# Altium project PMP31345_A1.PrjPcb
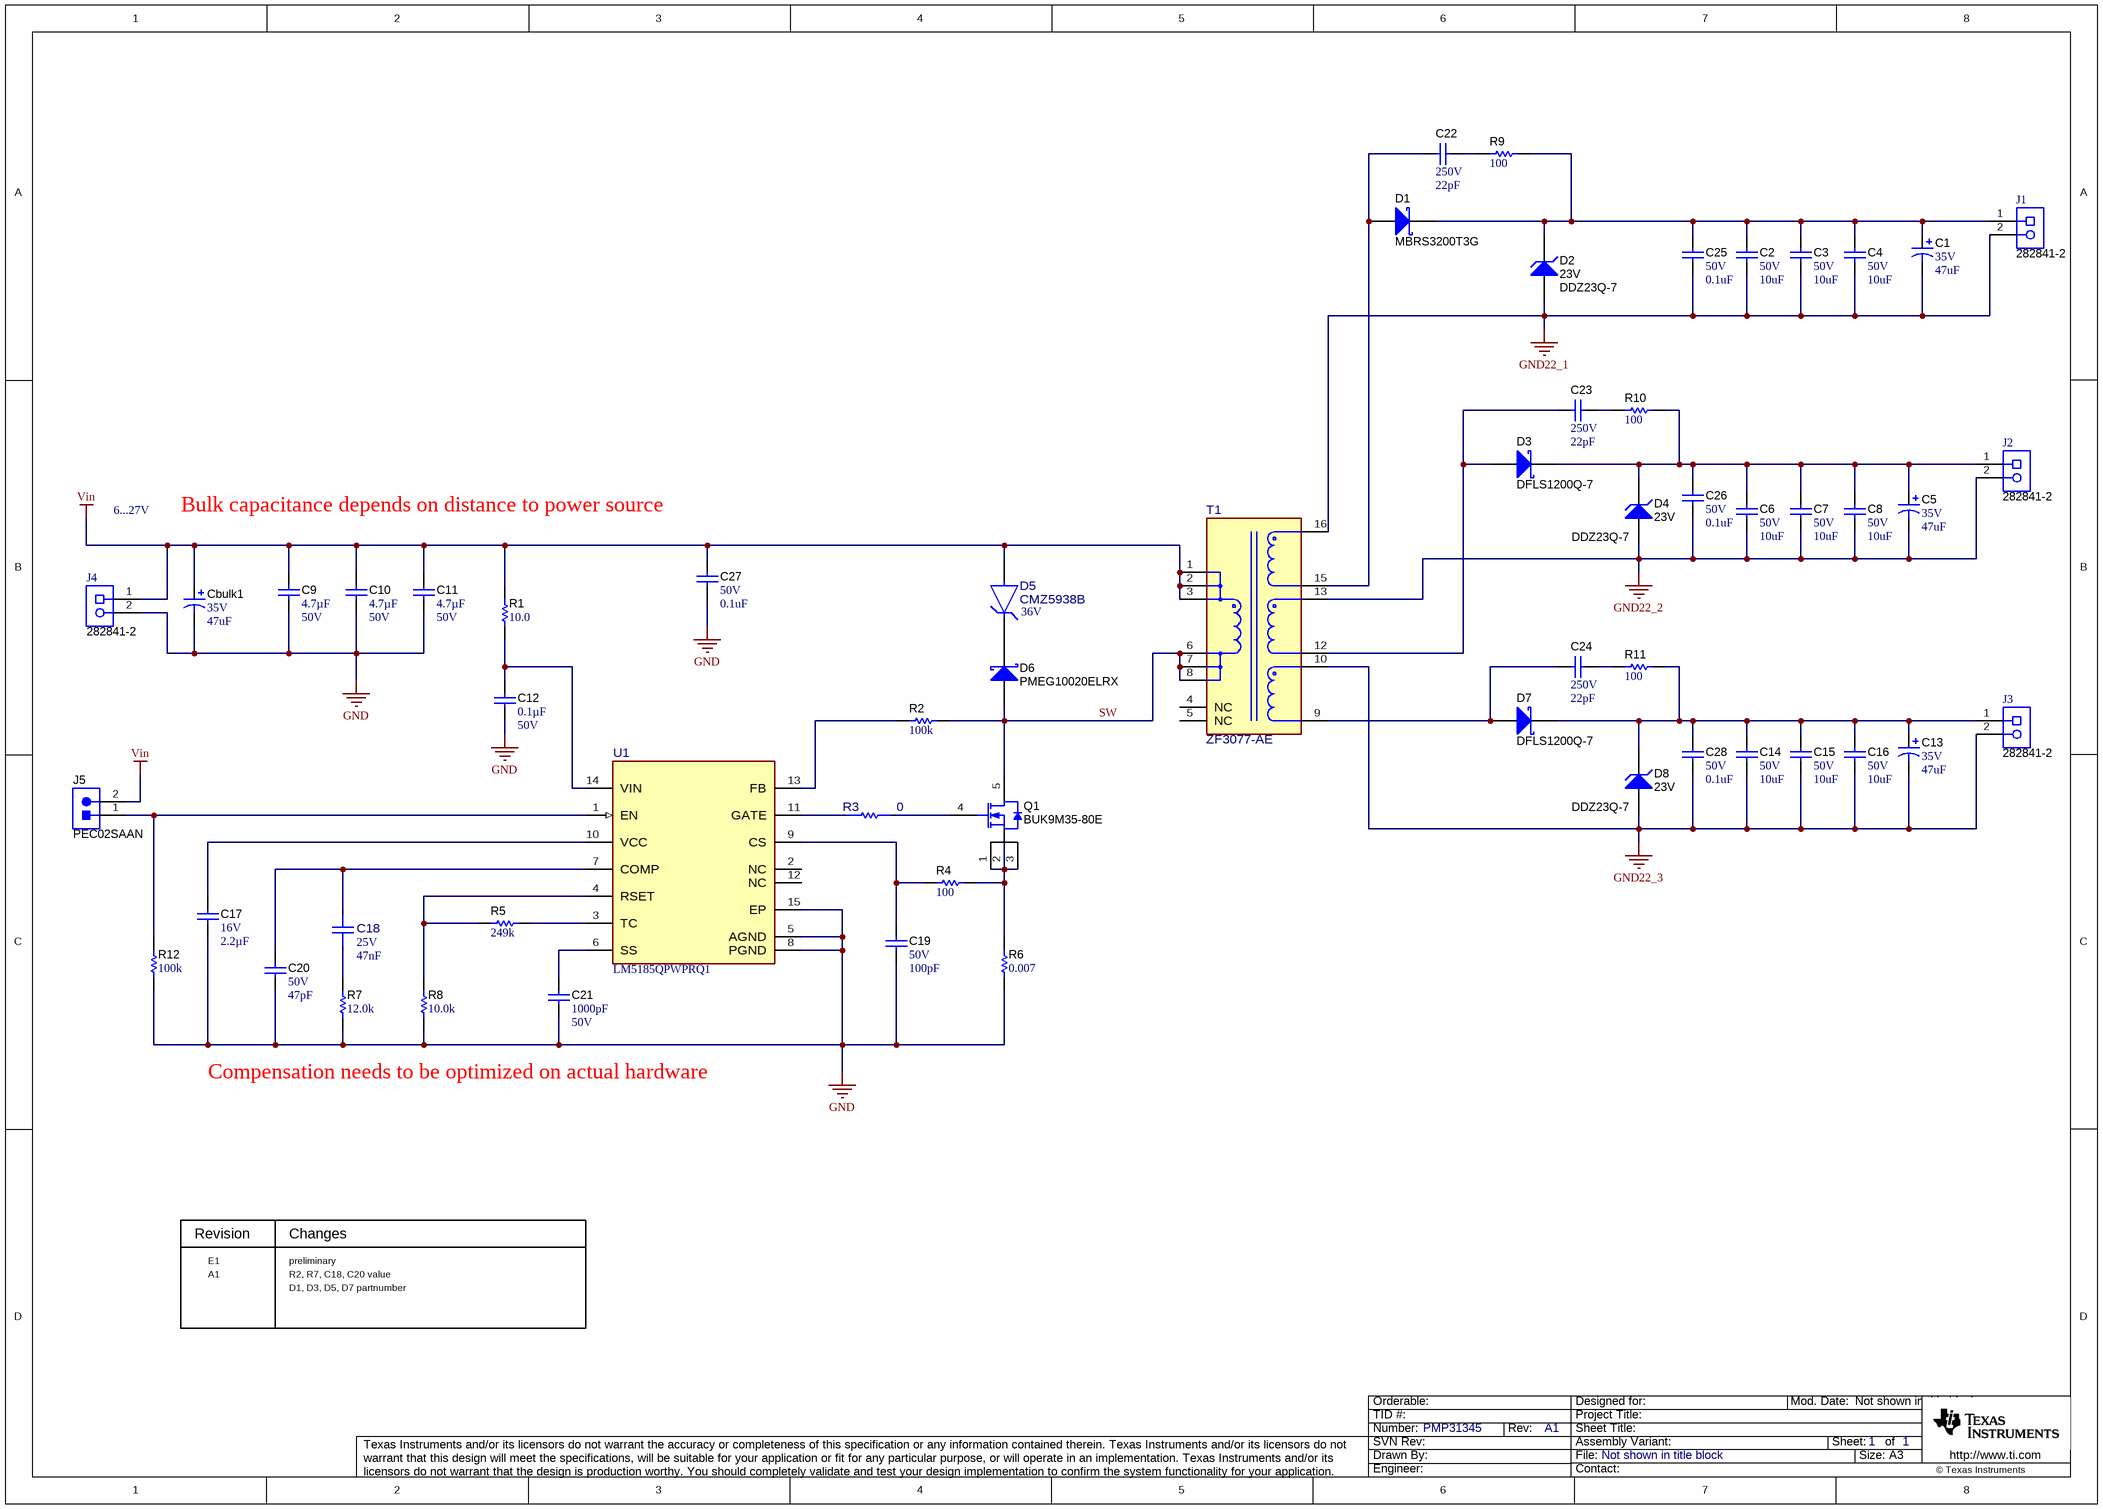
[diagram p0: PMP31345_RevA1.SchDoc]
PRJ_Number: PMP31345; SCH_Rev: A1
1 sheet, 57 parts. Net scope: global (net labels, ports and power ports of the same name join across sheets).
Board file: PMP31345_E1.PcbDoc

## Sheet PMP31345_RevA1.SchDoc
size A3; Date: Not shown in title block; ApprovedBy: Not shown in title block; CheckedBy: Not shown in title block; Author: Not shown in title block; CompanyName: Not shown in title block; Engineer: Not shown in title block; Organization: Not shown in title block; Address1: Not shown in title block; Address2: Not shown in title block; Address3: Not shown in title block; Address4: Not shown in title block; DocumentNumber: 1; Revision: Use project parameter SCH_Rev; SheetNumber: 1; SheetTotal: 1; PageSetup: Record=PageOptions¦CenterHorizontal=True¦CenterVertical=True¦PrintScale=0.69¦XCorrection=1.00¦YCorrection=1.00¦PrintKind=0¦BorderSize=5000000¦LeftOffset=0¦BottomOffset=0¦Orientation=2¦PaperLength=1000¦PaperWidth=1000¦Scale=100¦PaperSource=15¦PrintQuality=600¦MediaType=1¦DitherType=10¦PaperKind=Letter¦PrintScaleMode=1

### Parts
C1  VDC_V: 35V  ValueDisplayed: 47uF  [SM_RADIAL_D]  (hidden comment: EEE-FK1V470P)
C2  VDC_V: 50V  ValueDisplayed: 10uF  [1210_270]  (hidden comment: UMJ325KB7106KMHT)
C3  VDC_V: 50V  ValueDisplayed: 10uF  [1210_270]  (hidden comment: UMJ325KB7106KMHT)
C4  VDC_V: 50V  ValueDisplayed: 10uF  [1210_270]  (hidden comment: UMJ325KB7106KMHT)
C5  VDC_V: 35V  ValueDisplayed: 47uF  [SM_RADIAL_D]  (hidden comment: EEE-FK1V470P)
C6  VDC_V: 50V  ValueDisplayed: 10uF  [1210_270]  (hidden comment: UMJ325KB7106KMHT)
C7  VDC_V: 50V  ValueDisplayed: 10uF  [1210_270]  (hidden comment: UMJ325KB7106KMHT)
C8  VDC_V: 50V  ValueDisplayed: 10uF  [1210_270]  (hidden comment: UMJ325KB7106KMHT)
C9  ValueDisplayed: 4.7µF  VDC_V: 50V  [1210_270]  (hidden comment: GCM32ER71H475KA55L)
C10  ValueDisplayed: 4.7µF  VDC_V: 50V  [1210_270]  (hidden comment: GCM32ER71H475KA55L)
C11  ValueDisplayed: 4.7µF  VDC_V: 50V  [1210_270]  (hidden comment: GCM32ER71H475KA55L)
C12  ValueDisplayed: 0.1µF  VDC_V: 50V  [0402]  (hidden comment: CGA2B3X7R1H104K050BD)
C13  VDC_V: 35V  ValueDisplayed: 47uF  [SM_RADIAL_D]  (hidden comment: EEE-FK1V470P)
C14  VDC_V: 50V  ValueDisplayed: 10uF  [1210_270]  (hidden comment: UMJ325KB7106KMHT)
C15  VDC_V: 50V  ValueDisplayed: 10uF  [1210_270]  (hidden comment: UMJ325KB7106KMHT)
C16  VDC_V: 50V  ValueDisplayed: 10uF  [1210_270]  (hidden comment: UMJ325KB7106KMHT)
C17  VDC_V: 16V  ValueDisplayed: 2.2µF  [0402]  (hidden comment: GRT155C81C225ME13D)
C18  VDC_V: 25V  ValueDisplayed: 47nF  [FP-GCM155R71E473KA55D_0402-MFG]  (hidden comment: GCM155R71E473KA55D)
C19  VDC_V: 50V  ValueDisplayed: 100pF  [0402]  (hidden comment: CGA2B2C0G1H101J050BA)
C20  VDC_V: 50V  ValueDisplayed: 47pF  [0402]  (hidden comment: CGA2B2NP01H470J050BA)
C21  ValueDisplayed: 1000pF  VDC_V: 50V  [0402]  (hidden comment: CGA2B2X8R1H102K050BA)
C22  VDC_V: 250V  ValueDisplayed: 22pF  [0603]  (hidden comment: 251R14S220JV4T)
C23  VDC_V: 250V  ValueDisplayed: 22pF  [0603]  (hidden comment: 251R14S220JV4T)
C24  VDC_V: 250V  ValueDisplayed: 22pF  [0603]  (hidden comment: 251R14S220JV4T)
C25  VDC_V: 50V  ValueDisplayed: 0.1uF  [0402]  (hidden comment: GCM155R71H104KE02D)
C26  VDC_V: 50V  ValueDisplayed: 0.1uF  [0402]  (hidden comment: GCM155R71H104KE02D)
C27  VDC_V: 50V  ValueDisplayed: 0.1uF  [0402]  (hidden comment: GCM155R71H104KE02D)
C28  VDC_V: 50V  ValueDisplayed: 0.1uF  [0402]  (hidden comment: GCM155R71H104KE02D)
Cbulk1  VDC_V: 35V  ValueDisplayed: 47uF  [SM_RADIAL_D]  (hidden comment: EEE-FK1V470P)
D1  MBRS3200T3G  [SMB]
D2  DDZ23Q-7  value 23V  [SOD-123]
D3  DFLS1200Q-7  [FP-DFLS1200Q-7_PowerDI123-MFG]
D4  DDZ23Q-7  value 23V  [SOD-123]
D5  CMZ5938B  Vz_V: 36V  [FP-SMAJ5926B-TP_SMA-MFG]
D6  PMEG10020ELRX  [SOD-123W]
D7  DFLS1200Q-7  [FP-DFLS1200Q-7_PowerDI123-MFG]
D8  DDZ23Q-7  value 23V  [SOD-123]
J1  282841-2  [TEC_282841-2]
J2  282841-2  [TEC_282841-2]
J3  282841-2  [TEC_282841-2]
J4  282841-2  [TEC_282841-2]
J5  PEC02SAAN  [CONN_PEC02SAAN]
Q1  BUK9M35-80E  [LFPAK33]
R1  ValueDisplayed: 10.0  [0603]  (hidden comment: CRCW060310R0FKEA)
R2  ValueDisplayed: 100k  [0603]  (hidden comment: CRCW0603100KFKEA)
R3  0  [FP-ERJ-H3G0R00V_0603-MFG]
R4  ValueDisplayed: 100  [0402]  (hidden comment: RMCF0402JT100R)
R5  ValueDisplayed: 249k  [0402]  (hidden comment: CRCW0402249KFKED)
R6  ValueDisplayed: 0.007  [PE1206]  (hidden comment: PE1206FRF470R007L)
R7  ValueDisplayed: 12.0k  [0402]  (hidden comment: CRCW040212K0FKED)
R8  ValueDisplayed: 10.0k  [0402]  (hidden comment: ERJPA2F1002X)
R9  ValueDisplayed: 100  [1206]  (hidden comment: RC1206FR-07100RL)
R10  ValueDisplayed: 100  [1206]  (hidden comment: RC1206FR-07100RL)
R11  ValueDisplayed: 100  [1206]  (hidden comment: RC1206FR-07100RL)
R12  ValueDisplayed: 100k  [0402]  (hidden comment: RMCF0402FT100K)
T1  ZF3077-AE  [FP-ZF3077-AE_SMD16-MFG]
U1  LM5185QPWPRQ1  [PWP0014G-MFG]

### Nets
GND: C9.2 C10.2 C11.2 C12.2 C17.2 C19.2 C20.2 C21.2 C27.2 Cbulk1.2(-) J4.2 R6.1 R7.1 R8.1 R12.1 U1.5(AGND) U1.8(PGND) U1.15(EP)
GND22_1: C1.2(-) C2.2 C3.2 C4.2 C25.2 D2.2(A) J1.2 T1.16
GND22_2: C5.2(-) C6.2 C7.2 C8.2 C26.2 D4.2(A) J2.2 T1.13
GND22_3: C13.2(-) C14.2 C15.2 C16.2 C28.2 D8.2(A) J3.2 T1.10
Vin: C9.1 C10.1 C11.1 C27.1 Cbulk1.1(+) D5.2(ANODE) J4.1 J5.2 R1.2 T1.1 T1.2 T1.3
SW: D6.2(A) Q1.5(D) R2.2 T1.6 T1.7 T1.8
NetC1_1: C1.1(+) C2.1 C3.1 C4.1 C25.1 D1.1(K) D2.1(K) J1.1 R9.2
NetC5_1: C5.1(+) C6.1 C7.1 C8.1 C26.1 D3.1(K) D4.1(K) J2.1 R10.2
NetC12_1: C12.1 R1.1 U1.14(VIN)
NetC13_1: C13.1(+) C14.1 C15.1 C16.1 C28.1 D7.1(K) D8.1(K) J3.1 R11.2
NetC17_1: C17.1 U1.10(VCC)
NetC18_1: C18.1 R7.2
NetC18_2: C18.2 C20.1 U1.7(COMP)
NetC19_1: C19.1 R4.1 U1.9(CS)
NetC21_1: C21.1 U1.6(SS)
NetC22_1: C22.1 R9.1
NetC22_2: C22.2 D1.2(A) T1.15
NetC23_1: C23.1 R10.1
NetC23_2: C23.2 D3.2(A) T1.12
NetC24_1: C24.1 R11.1
NetC24_2: C24.2 D7.2(A) T1.9
NetD5_1: D5.1(CATHODE) D6.1(K)
NetJ5_1: J5.1 R12.2 U1.1(EN)
NetQ1_1: Q1.1(S) Q1.2(S) Q1.3(S) R4.2 R6.2
NetQ1_4: Q1.4(G) R3.2
NetR2_1: R2.1 U1.13(FB)
NetR3_1: R3.1 U1.11(GATE)
NetR5_1: R5.1 R8.2 U1.4(RSET)
NetR5_2: R5.2 U1.3(TC)

Not connected (* = marked no-connect by the designer): T1 4(NC) 5(NC); U1 2(NC) 12(NC)

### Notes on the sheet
- 6...27V
- Bulk capacitance depends on distance to power source
- Compensation needs to be optimized on actual hardware
- Revision
- E1
- Changes
- preliminary
- A1
- R2, R7, C18, C20 value
- D1, D3, D5, D7 partnumber

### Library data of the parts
C1 C5 C13 Cbulk1 = CMP-0010730-1: CAP, AL, 47 uF, 35 V, +/- 20%, 0.36 ohm, AEC-Q200 Grade 2, SMD; Manufacturer: Panasonic; TaMin_C: -55°C; ESR_ohm: 0.36; Polarized: Y; SizeAreaWB_mm2: 84.28; U/M: EA; Value: 47uF; TaMax_C: 105°C; SizeZ_mm: 5.4; SizeX_mm: 7.8; SizeY_mm: 6.6; Cap_Case: D; SizeArea_mm2: 51.48; CompType: Capacitor; Cap_F: 47µF; IRMS_A: 240mA; AEC Grade: 2; AEC Category: Q200
C2-C4 C6-C8 C14-C16 = CMP-0009257-2: CAP, CERM, 10 uF, 50 V, +/- 10%, X7R, AEC-Q200 Grade 1, 1210; Manufacturer: Taiyo Yuden; TaMin_C: -55°C; Polarized: N; SizeAreaWB_mm2: 14.7; Value1: Unknown; U/M: EA; Value: 10uF; TaMax_C: 125°C; SizeZ_mm: 2.7; SizeX_mm: 3.2; SizeY_mm: 2.5; Cap_Case: 1210; SizeArea_mm2: 8; AEC Qualified: Y; Cap_F: 10µF; AEC Grade: 1; AEC Category: Q200
C9-C11 = CMP-0750153-1: CAP, CERM, 4.7 µF, 50 V,+/- 10%, X7R, AEC-Q200 Grade 1, 1210; Manufacturer: MuRata; Polarized: N; TaMin_C: -55°C; TaMax_C: 125°C; SizeAreaWB_mm2: 14.7; SizeY_mm: 2.5; AEC Category: Q200; Value: 4.7uF; Cap_Case: 1210; AEC Qualified: Y; AEC Grade: 1; SizeArea_mm2: 8; SizeZ_mm: 2.7; U/M: EA; SizeX_mm: 3.2
C12 = CMP-0084548-1: CAP, CERM, 0.1 µF, 50 V,+/- 10%, X7R, AEC-Q200 Grade 1, 0402; Manufacturer: TDK; SizeZ_mm: 0.6; TaMax_C: 125°C; Cap_F: 100nF; Polarized: N; SizeX_mm: 1; Value: 0.1uF; AEC Category: Q200; TaMin_C: -55°C; SizeArea_mm2: 0.5; SizeAreaWB_mm2: 3; U/M: EA; AEC Qualified: Y
C17 = CMP-0860190-1: CAP, CERM, 2.2 µF, 16 V,+/- 20%, X6S, AEC-Q200 Grade 2, 0402; Manufacturer: MuRata; SizeArea_mm2: 0.5; Value: 2.2uF; AEC Category: Q200; AEC Qualified: Y; TaMin_C: -55°C; SizeX_mm: 1; SizeAreaWB_mm2: 3; Polarized: N; SizeZ_mm: 0.6; U/M: EA; AEC Grade: 2; TaMax_C: 105°C
C18 = CMP-0120705-1: Ceramic Capacitor for Automotive 47nF ±10% 25VDC X7R 0402 Paper T/R; Manufacturer: Murata; TempCo: 15%; Tolerance_%: 0.1%; SizeZ_mm: 0.55mm; AEC Qualified: Yes; AEC Grade: Grade 1
C19 = CMP-0006308-2: CAP, CERM, 100 pF, 50 V, +/- 5%, C0G/NP0, AEC-Q200 Grade 1, 0402; Manufacturer: TDK; TaMin_C: -55°C; Polarized: N; SizeAreaWB_mm2: 3; Value1: Unknown; U/M: EA; Value: 100pF; TaMax_C: 125°C; SizeZ_mm: 0.6; SizeX_mm: 1; SizeY_mm: 0.5; AEC Qualified: Y; AEC Category: Q200
C20 = CMP-0006312-2: CAP, CERM, 47 pF, 50 V, +/- 5%, C0G/NP0, AEC-Q200 Grade 0, 0402; Manufacturer: TDK; Value1: Unknown; AEC Grade: 0; AEC Category: Q200; TaMin_C: -55°C; SizeY_mm: 0.5; Polarized: N; U/M: EA; SizeZ_mm: 0.6; AEC Qualified: Y; SizeAreaWB_mm2: 3; TaMax_C: 150°C; SizeX_mm: 1; Value: 47pF
C21 = CMP-0860997-1: CAP, CERM, 1000 pF, 50 V,+/- 10%, X8R, AEC-Q200 Grade 0, 0402; Manufacturer: TDK; SizeArea_mm2: 0.5; U/M: EA; SizeX_mm: 1; Polarized: N; AEC Grade: 0; AEC Qualified: Y; TaMin_C: -55°C; Value: 1000pF; TaMax_C: 150°C; SizeZ_mm: 0.6; Cap_F: 1nF; SizeAreaWB_mm2: 3; AEC Category: Q200
C22-C24 = CMP-0081187-1: CAP, CERM, 22 pF, 250 V,+/- 5%, C0G/NP0, AEC-Q200 Grade 1, 0603; Manufacturer: Johanson Technology; TaMin_C: -55°C; Polarized: N; SizeAreaWB_mm2: 4.68; U/M: EA; Value: 22pF; TaMax_C: 125°C; SizeZ_mm: 1; SizeX_mm: 1.6; SizeY_mm: 0.8; SizeArea_mm2: 1.28; AEC Qualified: Y; AEC Category: Q200
C25-C28 = CMP-0006356-2: CAP, CERM, 0.1 uF, 50 V, +/- 10%, X7R, AEC-Q200 Grade 1, 0402; Manufacturer: MuRata; TaMin_C: -55°C; Polarized: N; SizeAreaWB_mm2: 3; Value1: Unknown; U/M: EA; Value: 0.1uF; TaMax_C: 125°C; SizeZ_mm: 0.6; SizeX_mm: 1; SizeY_mm: 0.5; AEC Qualified: Y; Cap_F: 100nF; AEC Category: Q200
D1 = CMP-0028599-2: Diode, Schottky, 200 V, 3 A, SMB; Manufacturer: ON Semiconductor; Value2: 0.84V; Green_REACh: Incomplete; Value1: 3A; SizeAreaWB_mm2: 44.156; RJC_CperW: 62; TJmax_C: 175°C; Vr_V: 200V; SizeY_mm: 3.81; Vf_V: 840mV; SizeX_mm: 5.6; SizeArea_mm2: 21.336; Green_Lifecycle: Not Set; AEC Category: Q101; SizeZ_mm: 2.6; Value: 200V
D2 D4 D8 = CMP-0085153-1: Diode, Zener, 23 V, 500 mW, AEC-Q101, SOD-123; Manufacturer: Diodes Inc.; SizeArea_mm2: 6.545; SizeX_mm: 3.85; Power_W: 500mW; SizeZ_mm: 1.35; RJA_CperW: 425; AEC Category: Q101; Value1: 0.5W; SizeAreaWB_mm2: 13.095; SizeY_mm: 1.7; AEC Qualified: Y
D3 D7 = CMP-0086794-2: DIODE SCHOTTKY 200V POWERDI123; Manufacturer: Diodes; AEC Category: Q101; TJmax_C: 150°C; AEC Qualified: Yes; SizeZ_mm: 1mm; Symbol Name: SYM-DFLS1200Q-7
D5 = CMP-0094824-1: Zener Diode 36 V 1.5 W ±5% Surface Mount DO-214AC (SMA); PartNumber: CMZ5938B TR13 PBFREE; Manufacturer: Central Semiconductor Corp; AEC Qualified: No; Vr_V: 27.4V; TJmax_C: 150°C; SizeZ_mm: 2.44mm; Zener Impedance: 38Ω; Max Reverse Leakage Current: 1uA; Standoff Height: 0.051mm; Power_W: 1.5W
D6 = CMP-0028977-2: Diode, Schottky, 100 V, 2 A, AEC-Q101, SOD-123W; Manufacturer: Nexperia; SizeY_mm: 1.7; Value2: 0.83V; Vf_V: 830mV; SizeZ_mm: 1; SizeAreaWB_mm2: 12.15; Value1: 2A; Vr_V: 100V; TJmax_C: 175°C; SizeArea_mm2: 5.95; AEC Category: Q101; AEC Qualified: Y; Value: 100V; SizeX_mm: 3.5
J1-J4 = CMP-0054973-1: Terminal Block, 2x1, 5.08mm, TH; Manufacturer: TE Connectivity; CNHeader: FALSE; Green_Lifecycle: Active; Green_REACh: Passed; CT: TRUE
J5 = CMP-0002337-1: Header, 100mil, 2x1, Tin, TH; Manufacturer: Sullins Connector Solutions; CNHeader: TRUE; Current_A: 3A; Green_Lifecycle: Not Set; Shrouded: N; Gender: Male; Green_REACh: Incomplete; Voltage_V: 1.8kV; Row_Count: 1; Pitch_mm: 2.54; CT: FALSE; Cert_UL: Y
Q1 = CMP-0078414-2: MOSFET, N-CH, 30 V, 70 A, AEC-Q101, 3.4x0.9x2.7mm; PartNumber: BUK9M6R6-30EX; Manufacturer: Nexperia; Alternate Manufacturer: None; ChType: N; QgTyp_nC: 18; SizeAreaWB_mm2: 18.49; SizeArea_mm2: 10.89; IdsMax_A: 70A; AEC Qualified: Y; VdsMax_V: 30V; Vgs_V: 10V; AEC Category: Q101; Value: 30V; SizeZ_mm: 0.9; SizeY_mm: 3.3; Value2: 18 nC; Value1: ? ohm
R1 = CMP-0022003-4: RES, 10.0, 1%, 0.1 W, AEC-Q200 Grade 0, 0603; Manufacturer: Vishay-Dale; Power_W: 100mW; TempCo: 100 ppm/C; Value_Code: 10R0; Value: 10.0; EIA_Code: E96; Res_ohm: 10; SizeX_mm: 1.6; SizeY_mm: 0.8; SizeZ_mm: 1; Value2: 0.1W; SizeArea_mm2: 1.28; AEC Qualified: Y; VDC_V: 75V; AEC Category: Q200; AEC Grade: 0
R2 = CMP-0021990-4: RES, 100 k, 1%, 0.1 W, AEC-Q200 Grade 0, 0603; Manufacturer: Vishay-Dale; Power_W: 100mW; TempCo: 100 ppm/C; Value: 100k; EIA_Code: E96; SizeX_mm: 1.6; SizeY_mm: 0.8; SizeZ_mm: 1; Value2: 0.1W; SizeArea_mm2: 1.28; AEC Qualified: Y; VDC_V: 75V; AEC Category: Q200; AEC Grade: 0
R3 = CMP-0097467-1: 0 Ohms Jumper 0.125W, 1/8W Chip Resistor 0603 (1608 Metric) Automotive AEC-Q200 Thick Film; Manufacturer: Panasonic; PartNumber: ERJ-H3G0R00V; VDC_V: 75V; Power_W: 125mW; AEC Qualified: Yes; SizeZ_mm: 0.55mm; AEC Grade: Grade 0
R4 = CMP-0026763-1: RES, 100, 1%, 0.063 W, AEC-Q200 Grade 0, 0402; Manufacturer: Stackpole Electronics Inc; Power_W: 63mW; TempCo: 100 ppm/C; Value_Code: 100R; U/M: EA; Value: 100; EIA_Code: E96; SizeX_mm: 1; SizeY_mm: 0.5; SizeZ_mm: 0.6; Value2: 0.063W; AEC Qualified: Y; AEC Grade: 0; AEC Category: Q200
R5 = CMP-0026193-2: RES, 249 k, 1%, 0.063 W, AEC-Q200 Grade 0, 0402; Manufacturer: Vishay-Dale; Power_W: 63mW; TempCo: 100 ppm/C; Value: 249k; EIA_Code: E96; SizeX_mm: 1; SizeY_mm: 0.5; SizeZ_mm: 0.6; Value2: 0.063W; AEC Qualified: Y; VDC_V: 50V; AEC Category: Q200; AEC Grade: 0
R6 = CMP-0017834-2: RES, 0.007, 1%, 1 W, AEC-Q200 Grade 0, 1206; Manufacturer: Yageo America; Power_W: 1W; TempCo: 100 ppm/C; Value_Code: 7L000; U/M: EA; Value: 0.007; EIA_Code: E96; Res_ohm: 7m; SizeX_mm: 3.2; SizeY_mm: 1.6; SizeZ_mm: 0.89; SizeArea_mm2: 5.12; AEC Qualified: Y; AEC Grade: 0; AEC Category: Q200
R7 = CMP-0025990-3: RES, 12.0 k, 1%, 0.063 W, AEC-Q200 Grade 0, 0402; Manufacturer: Vishay-Dale; Value_Code: 12k0; SizeArea_mm2: 0.5; AEC Qualified: Y; AEC Category: Q200; Res_ohm: 12k; Value: 12.0k; SizeZ_mm: 0.6; TempCo: 100 ppm/C; AEC Grade: 0; Power_W: 63mW; VDC_V: 50V; Value2: 0.063W; SizeX_mm: 1
R8 = CMP-0078779-1: RES, 10.0 k, 1%, 0.2 W, AEC-Q200 Grade 0, 0402; Manufacturer: Panasonic; Value_Code: 10k0; SizeArea_mm2: 0.5; AEC Qualified: Y; AEC Category: Q200; Res_ohm: 10k; Value: 10.0k; SizeZ_mm: 0.6; EIA_Code: E96; TempCo: 100 ppm/C; AEC Grade: 0; Power_W: 200mW; VDC_V: 50V; Value2: 0.2W; SizeX_mm: 1
R9-R11 = CMP-0017837-2: RES, 100, 1%, 0.25 W, 1206; Manufacturer: Yageo America; Power_W: 250mW; TempCo: 100 ppm/C; Value_Code: 100R; U/M: EA; Value: 100; EIA_Code: E96; SizeX_mm: 3.2; SizeY_mm: 1.6; SizeZ_mm: 1.35; Value2: 0.25W; SizeArea_mm2: 5.12; VDC_V: 200V; AEC Category: Q200
R12 = CMP-0026753-1: RES, 100 k, 1%, 0.063 W, AEC-Q200 Grade 0, 0402; Manufacturer: Stackpole Electronics Inc; Power_W: 63mW; TempCo: 100 ppm/C; U/M: EA; Value: 100k; EIA_Code: E96; SizeX_mm: 1; SizeY_mm: 0.5; SizeZ_mm: 0.6; Value2: 0.063W; AEC Qualified: Y; VDC_V: 50V; AEC Grade: 0; AEC Category: Q200
T1 = CMP-0122818-1: Transformer; Manufacturer: Coilcraft; SizeZ_mm: 12.5mm; AEC Qualified: No; Frequency_Fixed: 300kHz
U1 = CMP-0120083-1: 100-VIN, PSR, Flyback, Automotive, DC/DC Controller With Low IQ and Low EMI; Manufacturer: Texas Instruments; SizeZ_mm: 1.2mm; AEC Qualified: Yes; AEC Grade: Grade 1; Max Supply Voltage: 100V; Min Supply Voltage: 4.5V; Nominal Supply Current: 25-425uA; Number Of Outputs: 1; Output Type: AdjustableProgrammable; Standoff Height: 0.05mm; Switching Frequency: 10-350kHz; TaMax_C: +125°C; TaMin_C: -40°C; TJmax_C: +150°C

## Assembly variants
Built and tested: not fitted C3 C4 C7 C8 C15 C16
